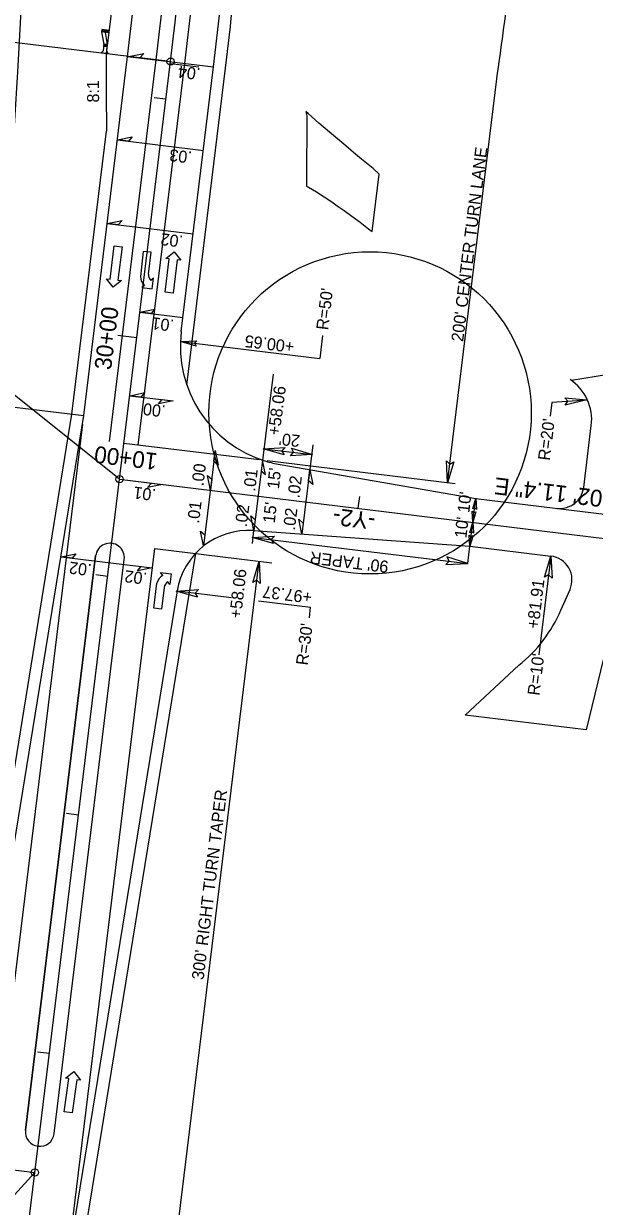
# Model space of a CAD drawing. Extents: x 472216 to 481979, y 489069 to 507339.
# Drawn here: x 481341.2 to 481578.5, y 490719.3 to 491211.4 of the extents above; entities that cross this region are included whole.
import ezdxf

# ---------------------------------------------------------------- set-up
doc = ezdxf.new("R2010")
doc.units = 0
for name, color, linetype in [('Old_Level_12', 7, 'Continuous'), ('Prop Drainage Structure Box Number Symbol CELL', 7, 'Continuous'), ('Prop Drainage Structure Drop Inlet Grate 2 Narrow Slots and Sag Grates 840 24 CELL', 7, 'Continuous'), ('Prop Drainage Structure Drop Inlet Grate 2 Wide Slots and Sag Grates 840 22 Label', 7, 'Continuous'), ('Prop Drainage Structure Outlet Berm Ditch 850 10 CELL', 7, 'Continuous'), ('Prop Drainage Structure Pipe CSP 15in', 7, 'Continuous'), ('Prop Drainage Structure Pipe Plug CELL', 7, 'Continuous'), ('Prop Drainage Structure Pipe RCP 15in Class III Label', 7, 'Continuous'), ('Prop Drainage Structure Pipe RCP 24in Class III Label', 7, 'Continuous'), ('Prop Drainage Structure Pipe Side Drain 15in Label', 7, 'Continuous'), ('Prop Earthen Structure Head Ditch', 7, 'Continuous'), ('Prop Erosion Embankment Toe Protection CELL', 7, 'Continuous'), ('Prop Erosion Embankment Toe Protection Label', 7, 'Continuous'), ('Sheet Block Revision CELL', 7, 'Continuous'), ('Sheet North Arrow Point CELL', 7, 'Continuous'), ('Sheet PE Seal Cell', 7, 'Continuous'), ('Sheet Plan And Profile CELL', 7, 'Continuous'), ('Sheet Plot Border Outside CELL', 7, 'Continuous'), ('Sheet Profile Grid Major CELL', 7, 'Continuous'), ('Sheet Profile Grid Minor CELL', 7, 'Continuous')]:
    doc.layers.add(name, color=color, linetype=linetype)

msp = doc.modelspace()

# ---------------------------------------------------------------- linework, layer by layer
at = {"layer": 'Old_Level_12'}
for p, q in [((481400.78, 491195.76), (481253.89, 491213.7)), ((481381.05, 491021.87), (481307.76, 491080.53)), ((481345.82, 490733.42), (481205.56, 490579.57))]:
    msp.add_line(p, q, dxfattribs=at)
for centre in [(481402.27, 491195.58), (481402.27, 491195.58), (481381.05, 491021.87), (481381.05, 491021.87), (481345.82, 490733.42)]:
    msp.add_circle(centre, 1.5, dxfattribs=at)
at = {"layer": 'Prop Drainage Structure Box Number Symbol CELL'}
msp.add_line((481414.07, 491193.23), (481402.16, 491194.68), dxfattribs=at)
at = {"layer": 'Prop Drainage Structure Drop Inlet Grate 2 Narrow Slots and Sag Grates 840 24 CELL'}
msp.add_line((481440.51, 491029.78), (481440.45, 491029.76), dxfattribs=at)
for points in [[(481384.92, 491197.69), (481391.12, 491198.95), (481389.51, 491197.13)], [(481380.15, 491163.01), (481386.35, 491164.27), (481384.75, 491162.45)], [(481375.91, 491128.27), (481382.11, 491129.53), (481380.5, 491127.71)], [(481389.53, 491091.35), (481395.73, 491092.6), (481394.13, 491090.79)], [(481385.29, 491056.6), (481391.49, 491057.86), (481389.88, 491056.04)], [(481403.39, 491054.39), (481397.19, 491053.14), (481398.8, 491054.95)], [(481420.85, 491033.82), (481422.11, 491027.62), (481420.29, 491029.23)], [(481460.17, 491025.8), (481461.43, 491019.6), (481459.61, 491021.21)], [(481398.92, 491019.68), (481392.72, 491018.42), (481394.32, 491020.24)], [(481418.83, 491017.25), (481417.57, 491023.45), (481419.39, 491021.84)], [(481436.92, 491000.44), (481435.66, 491006.63), (481437.48, 491005.03)], [(481456.9, 490999), (481455.64, 491005.2), (481457.46, 491003.59)], [(481416, 490994.06), (481414.74, 491000.26), (481416.56, 490998.65)], [(481356.72, 490989.57), (481362.92, 490990.83), (481361.31, 490989.01)], [(481394.67, 490984.94), (481388.47, 490983.68), (481390.08, 490985.5)]]:
    msp.add_lwpolyline(points, close=True, dxfattribs=at)
msp.add_lwpolyline([(481440.45, 491029.76), (481439.91, 491025.36), (481441.73, 491023.75), (481440.51, 491029.78)], dxfattribs=at)
at = {"layer": 'Prop Drainage Structure Drop Inlet Grate 2 Wide Slots and Sag Grates 840 22 Label'}
for p, q in [((481384.4, 491197.75), (481420.13, 491193.39)), ((481380.15, 491163.01), (481415.89, 491158.65)), ((481375.91, 491128.27), (481411.65, 491123.91)), ((481389.53, 491091.35), (481407.4, 491089.16)), ((481444.88, 491065.58), (481436.92, 491000.44)), ((481385.29, 491056.6), (481403.16, 491054.42)), ((481441.09, 491034.54), (481460.94, 491032.11)), ((481461.44, 491036.18), (481456.9, 490999)), ((481420.85, 491033.82), (481416, 490994.06)), ((481381.05, 491021.86), (481398.92, 491019.68)), ((481356.72, 490989.57), (481394.67, 490984.94))]:
    msp.add_line(p, q, dxfattribs=at)
at = {"layer": 'Prop Drainage Structure Outlet Berm Ditch 850 10 CELL'}
for points in [[(481412.91, 491077.13), (481406.35, 491079.11), (481413.23, 491079.47), (481412.23, 491078.39)], [(481566.2, 491055.72), (481575.29, 491054.81), (481566.37, 491052.58), (481567.41, 491054.26)], [(481449.51, 491031.96), (481440.74, 491034.52), (481449.91, 491035.08), (481448.59, 491033.62)], [(481452.52, 491034.69), (481461.29, 491032.13), (481452.11, 491031.57), (481453.44, 491033.03)], [(481520.06, 491029.06), (481517.4, 491020.32), (481516.94, 491029.5), (481518.38, 491028.16)], [(481527.9, 491009.5), (481529.17, 491013.89), (481529.46, 491009.3), (481528.73, 491009.96)], [(481529.24, 491008.31), (481527.96, 491003.92), (481527.67, 491008.51), (481528.4, 491007.85)], [(481526.68, 490999.54), (481527.96, 491003.92), (481528.25, 490999.34), (481527.52, 491000)], [(481445, 490995.06), (481436.23, 490997.62), (481445.41, 490998.18), (481444.08, 490996.72)], [(481528.03, 490998.42), (481526.75, 490994.04), (481526.46, 490998.62), (481527.19, 490997.96)], [(481436.43, 490978.94), (481439.09, 490987.68), (481439.55, 490978.5), (481438.11, 490979.84)], [(481516.74, 490986.36), (481525.87, 490986.74), (481517.1, 490989.49), (481518.04, 490987.76)], [(481557.75, 490981.15), (481560.4, 490989.88), (481560.87, 490980.71), (481559.42, 490982.05)], [(481413.41, 490972.77), (481404.64, 490975.33), (481413.81, 490975.89), (481412.49, 490974.43)]]:
    msp.add_lwpolyline(points, close=True, dxfattribs=at)
at = {"layer": 'Prop Drainage Structure Pipe Plug CELL'}
for p, q in [((481381.69, 491248.57), (481375.88, 491202.18)), ((481373.64, 491208.91), (481373.51, 491207.92)), ((481373.51, 491207.92), (481375.16, 491208.72)), ((481376.55, 491207.54), (481373.51, 491207.92)), ((481373.51, 491207.92), (481374.45, 491202.86)), ((481376.68, 491208.53), (481373.64, 491208.91)), ((481375.03, 491207.73), (481373.64, 491208.91)), ((481375.16, 491208.72), (481375.03, 491207.73)), ((481376.68, 491208.53), (481375.03, 491207.73)), ((481375.03, 491207.73), (481375.94, 491202.68)), ((481375.16, 491208.72), (481376.55, 491207.54)), ((481374.45, 491202.86), (481374.33, 491201.87)), ((481374.33, 491201.87), (481375.94, 491202.68)), ((481375.82, 491201.68), (481374.33, 491201.87)), ((481374.37, 491200.25), (481374.59, 491202.29)), ((481374.45, 491202.86), (481374.39, 491202.37)), ((481375.94, 491202.68), (481374.45, 491202.86)), ((481375.82, 491201.68), (481374.45, 491202.86)), ((481374.59, 491202.29), (481375.2, 491202.22)), ((481375.2, 491202.22), (481375.8, 491202.16)), ((481375.8, 491202.16), (481375.58, 491200.12)), ((481373.39, 491199.17), (481374.37, 491200.25)), ((481376.32, 491198.86), (481373.39, 491199.17)), ((481375.58, 491200.12), (481376.32, 491198.86))]:
    msp.add_line(p, q, dxfattribs=at)
at = {"layer": 'Prop Drainage Structure Pipe RCP 15in Class III Label'}
for p, q in [((481376.91, 491037.48), (481396.31, 491196.3)), ((481388.82, 491036.02), (481408.22, 491194.85)), ((481341.92, 490751.02), (481371.1, 490989.94)), ((481371.1, 490989.94), (481341.92, 490751.02)), ((481353.84, 490749.57), (481383.02, 490988.48)), ((481353.84, 490749.57), (481383.02, 490988.48))]:
    msp.add_line(p, q, dxfattribs=at)
for centre, radius, start, end in [((479903.4, 491378.64), 1504, 353.03651, 0.24575), ((479903.4, 491378.64), 1516, 353.03651, 0.24575), ((481377.06, 490989.21), 6, 353.0365, 173.0365), ((481377.06, 490989.21), 6, 353.0365, 173.0365), ((481347.88, 490750.29), 6, 173.0365, 353.0365), ((481347.88, 490750.29), 6, 173.0365, 353.0365)]:
    msp.add_arc(centre, radius, start, end, dxfattribs=at)
at = {"layer": 'Prop Drainage Structure Pipe RCP 24in Class III Label'}
for p, q in [((481366.14, 491048.28), (481384.4, 491197.76)), ((481406.68, 491083.27), (481420.13, 491193.39)), ((481568.91, 491062.98), (481596.21, 491067.55)), ((481322.63, 490780.38), (481366.14, 491048.28)), ((481574.07, 491018.43), (481577.22, 491044.18)), ((481447.78, 491027.94), (481529.17, 491013.85)), ((481529.17, 491013.85), (481693.34, 490993.8)), ((481436.75, 491000.45), (481526.74, 490994)), ((481526.74, 490994), (481560.4, 490989.88)), ((481404.99, 490975.35), (481359.1, 490693.69)), ((481564.58, 490967.3), (481568.36, 490975.96)), ((481589.52, 490977.4), (481575.09, 490917.57)), ((481547.09, 490944.45), (481524.73, 490923.72)), ((481575.09, 490917.57), (481524.73, 490923.72))]:
    msp.add_line(p, q, dxfattribs=at)
for centre, radius, start, end in [((479903.4, 491378.64), 1492, 353.03651, 0.2515), ((479903.4, 491378.64), 1528, 353.03651, 0.25136), ((481456.31, 491077.21), 50, 173.0365, 253.1553), ((481557.37, 491046.61), 20, 353.0092, 56.5397), ((481456.31, 491077.21), 50, 253.1553, 260.1741), ((481564.14, 491019.65), 10, 263.0365, 353.0092), ((481434.6, 490970.53), 30, 85.8989, 170.7459), ((481559.19, 490979.96), 10, 336.4429, 83.0365), ((481509.58, 490991.28), 60, 308.6877, 336.4429)]:
    msp.add_arc(centre, radius, start, end, dxfattribs=at)
at = {"layer": 'Prop Drainage Structure Pipe Side Drain 15in Label'}
for p, q in [((481377.09, 491105.03), (481378.79, 491118.93)), ((481378.79, 491118.93), (481382.06, 491118.53)), ((481382.06, 491118.53), (481380.37, 491104.63)), ((481390.83, 491116.63), (481389.7, 491106.14)), ((481394.12, 491116.28), (481390.83, 491116.63)), ((481393.14, 491107.18), (481394.12, 491116.28)), ((481400.03, 491099.62), (481401.73, 491113.52)), ((481400.24, 491113.7), (481403.7, 491116.45)), ((481401.73, 491113.52), (481400.24, 491113.7)), ((481405, 491113.12), (481403.3, 491099.22)), ((481403.7, 491116.45), (481406.49, 491112.94)), ((481406.49, 491112.94), (481405, 491113.12)), ((481378.4, 491101.7), (481375.6, 491105.21)), ((481375.6, 491105.21), (481377.09, 491105.03)), ((481381.85, 491104.45), (481378.4, 491101.7)), ((481380.37, 491104.63), (481381.85, 491104.45)), ((481395.17, 491105.5), (481394.01, 491104.57)), ((481394.64, 491101.03), (481395.17, 491105.5)), ((481391.42, 491102.48), (481390.27, 491101.55)), ((481390.27, 491101.55), (481394.64, 491101.03)), ((481403.3, 491099.22), (481400.03, 491099.62)), ((481399.03, 490981.8), (481398.12, 490982.97)), ((481398.12, 490982.97), (481402.49, 490982.49)), ((481402.49, 490982.49), (481401.99, 490978.02)), ((481395.25, 490968.16), (481396.53, 490978.63)), ((481399.64, 490976.84), (481398.53, 490967.76)), ((481401.99, 490978.02), (481401.08, 490979.19)), ((481398.53, 490967.76), (481395.25, 490968.16)), ((481358.53, 490772.7), (481362.05, 490775.38)), ((481362.05, 490775.38), (481364.77, 490771.81)), ((481358.04, 490758.63), (481360.02, 490772.49)), ((481360.02, 490772.49), (481358.53, 490772.7)), ((481363.28, 490772.03), (481361.31, 490758.17)), ((481364.77, 490771.81), (481363.28, 490772.03)), ((481361.31, 490758.17), (481358.04, 490758.63))]:
    msp.add_line(p, q, dxfattribs=at)
for centre, radius, start, end in [((481394.94, 491106.37), 5.25, 182.5311, 227.8427), ((481396.37, 491106.82), 3.27, 173.855, 223.5132), ((481401.57, 490977.22), 5.25, 119.0478, 164.3595), ((481402.87, 490976.46), 3.27, 123.3774, 173.0356)]:
    msp.add_arc(centre, radius, start, end, dxfattribs=at)
at = {"layer": 'Prop Earthen Structure Head Ditch'}
for p, q in [((481458.54, 491174.82), (481458.72, 491173.87)), ((481458.72, 491173.87), (481458.93, 491172.77)), ((481486.08, 491124.85), (481489.01, 491148.81))]:
    msp.add_line(p, q, dxfattribs=at)
for points in [[(481489.01, 491148.81), (481486.48, 491151.06), (481484.45, 491152.74), (481481.72, 491155.02), (481478.35, 491157.83), (481475.12, 491160.52), (481470.78, 491164.1), (481468.29, 491166.17), (481463.91, 491170.01), (481459.46, 491173.99), (481458.54, 491174.82)], [(481458.93, 491172.77), (481458.75, 491146.35), (481458.74, 491143.79)], [(481458.74, 491143.79), (481459.58, 491143.34), (481462.97, 491141.34), (481466.11, 491139.36), (481469.28, 491137.23), (481471.56, 491135.64), (481474.49, 491133.57), (481477.68, 491131.25), (481481.05, 491128.72), (481484.56, 491126.03), (481486.08, 491124.85)]]:
    msp.add_lwpolyline(points, dxfattribs=at)
at = {"layer": 'Prop Erosion Embankment Toe Protection CELL'}
for p, q in [((481381.69, 491248.57), (481375.48, 491198.95)), ((481409, 491061.03), (481425.1, 491192.79)), ((481361.18, 491048.88), (481375.57, 491166.71)), ((481315.03, 490764.81), (481361.18, 491048.88)), ((481412.59, 490990.91), (481364.05, 490692.98))]:
    msp.add_line(p, q, dxfattribs=at)
msp.add_arc((479903.4, 491378.64), 1533, 353.03651, 357.21325, dxfattribs=at)
msp.add_spline([(481375.48, 491198.95), (481375.48, 491198.52), (481375.48, 491198.08), (481375.48, 491197.65), (481375.48, 491197.21), (481375.48, 491196.77), (481375.48, 491196.34), (481375.49, 491195.9), (481375.49, 491195.47), (481375.49, 491195.03), (481375.49, 491194.6), (481375.49, 491194.16), (481375.49, 491193.72), (481375.49, 491193.29), (481375.49, 491192.85), (481375.5, 491192.42), (481375.5, 491191.98), (481375.5, 491191.55), (481375.5, 491191.11), (481375.5, 491190.67), (481375.5, 491190.24), (481375.5, 491189.8), (481375.5, 491189.37), (481375.51, 491188.93), (481375.51, 491188.49), (481375.51, 491188.06), (481375.51, 491187.62), (481375.51, 491187.19), (481375.51, 491186.75), (481375.51, 491186.32), (481375.51, 491185.88), (481375.52, 491185.44), (481375.52, 491185.01), (481375.52, 491184.57), (481375.52, 491184.14), (481375.52, 491183.7), (481375.52, 491183.27), (481375.52, 491182.83), (481375.52, 491182.39), (481375.53, 491181.96), (481375.53, 491181.52), (481375.53, 491181.09), (481375.53, 491180.65), (481375.53, 491180.21), (481375.53, 491179.78), (481375.53, 491179.34), (481375.53, 491178.91), (481375.54, 491178.47), (481375.54, 491178.04), (481375.54, 491177.6), (481375.54, 491177.16), (481375.54, 491176.73), (481375.54, 491176.29), (481375.54, 491175.86), (481375.54, 491175.42), (481375.54, 491174.99), (481375.55, 491174.55), (481375.55, 491174.11), (481375.55, 491173.68), (481375.55, 491173.24), (481375.55, 491172.81), (481375.55, 491172.37), (481375.55, 491171.93), (481375.55, 491171.5), (481375.56, 491171.06), (481375.56, 491170.63), (481375.56, 491170.19), (481375.56, 491169.76), (481375.56, 491169.32), (481375.56, 491168.88), (481375.56, 491168.45), (481375.56, 491168.01), (481375.57, 491167.58), (481375.57, 491166.71)], degree=3, dxfattribs=at)
at = {"layer": 'Prop Erosion Embankment Toe Protection Label'}
for p, q in [((481329.34, 490746.99), (481365.71, 491044.78)), ((481359.1, 490693.69), (481395.65, 490992.98))]:
    msp.add_line(p, q, dxfattribs=at)
at = {"layer": 'Sheet Block Revision CELL'}
for p, q in [((481517.4, 491020.32), (481537.92, 491188.37)), ((481406.35, 491079.11), (481464.26, 491072.03)), ((481465.44, 491081.68), (481464.26, 491072.03)), ((481291.41, 491057.4), (481366.14, 491048.28)), ((481575.63, 491054.77), (481560.85, 491053.69)), ((481560.85, 491053.69), (481560.16, 491048.1)), ((481439.2, 491029.87), (481382.87, 491036.75)), ((481520.67, 491019.92), (481442.38, 491029.48)), ((481526.74, 490994), (481529.18, 491013.85)), ((481436.27, 490995.11), (481436.92, 491000.44)), ((481436.59, 490997.64), (481525.87, 490986.74)), ((481395.65, 490992.98), (481444.39, 490987.03)), ((481525.87, 490986.74), (481526.76, 490993.99)), ((481402.53, 490688.38), (481439.09, 490987.68)), ((481560.4, 490989.88), (481555.39, 490948.81)), ((481404.99, 490975.35), (481427.53, 490972.6)), ((481438.82, 490971.22), (481460.49, 490968.57)), ((481459.96, 490964.23), (481460.49, 490968.57))]:
    msp.add_line(p, q, dxfattribs=at)
msp.add_arc((478970.41, 491554.36), 2593.46, 351.88804, 352.74017, dxfattribs=at)
at = {"layer": 'Sheet North Arrow Point CELL'}
for p, q in [((481200.24, 489541.46), (481402.27, 491195.58)), ((481381.05, 491021.87), (481684.64, 490984.78)), ((481273.15, 490742.29), (481345.82, 490733.42))]:
    msp.add_line(p, q, dxfattribs=at)
for centre, radius, end in [((478448.7, 491360.28), 2895, 18.70399), ((479903.4, 491378.64), 1510, 12.98112)]:
    msp.add_arc(centre, radius, 353.03651, end, dxfattribs=at)
at = {"layer": 'Sheet PE Seal Cell'}
for p, q in [((481400.35, 491179.93), (481395.39, 491180.53)), ((481480.31, 491009.74), (481480.92, 491014.7)), ((481376.11, 490981.4), (481371.14, 490982.01)), ((481363.98, 490882.14), (481359.02, 490882.75)), ((481351.86, 490782.88), (481346.9, 490783.48))]:
    msp.add_line(p, q, dxfattribs=at)
at = {"layer": 'Sheet Plot Border Outside CELL'}
msp.add_circle((481485.2, 491049.44), 67.03, dxfattribs=at)
at = {"layer": 'Sheet Profile Grid Minor CELL'}
for p, q in [((481388.23, 491080.67), (481380.29, 491081.64)), ((481381.05, 491021.87), (481382.02, 491029.81)), ((481381.05, 491021.87), (481382.02, 491029.81)), ((481345.82, 490733.42), (481346.79, 490741.36))]:
    msp.add_line(p, q, dxfattribs=at)

# ---------------------------------------------------------------- texts
at = {"layer": 'Prop Drainage Structure Drop Inlet Grate 2 Narrow Slots and Sag Grates 840 24 CELL'}
for s, rotation, p in [('.04', 173.0359, (481414.89, 491192.81)), ('.03', 173.0359, (481411.36, 491158.09)), ('.02', 173.0359, (481407.69, 491123.12)), ('.01', 173.0359, (481403.94, 491088.16)), ('.00', 173.0359, (481400.37, 491052.46)), ('.00', 83.0368, (481415.9, 491018.81)), ('.01', 83.0368, (481437.42, 491016.58)), ('.02', 83.0368, (481455.79, 491013.76)), ('.01', 173.0359, (481396.42, 491017.68)), ('.01', 83.0368, (481414.07, 491003.26)), ('.02', 83.0368, (481433.94, 491001.81)), ('.02', 83.0368, (481453.92, 491000.38)), ('.02', 173.0359, (481369.64, 490986.44)), ('.02', 173.0359, (481392.71, 490982.87))]:
    msp.add_text(s, height=5, rotation=rotation, dxfattribs=at).set_placement(p)
at = {"layer": 'Prop Drainage Structure Drop Inlet Grate 2 Wide Slots and Sag Grates 840 22 Label'}
for s, rotation, p in [('+58.06', 82.3928, (481447.54, 491039.84)), ("20'", 173.7495, (481456.29, 491040.14)), ('+58.06', 83.6803, (481431.58, 490963.74))]:
    msp.add_text(s, height=5, rotation=rotation, dxfattribs=at).set_placement(p)
at = {"layer": 'Prop Drainage Structure Pipe CSP 15in'}
for s, rotation, p in [('8:1', 90.5984, (481372.56, 491178.58)), ("200' CENTER TURN LANE ", 82.8641, (481523.89, 491078.82)), ("R=50'", 83.0365, (481467.75, 491083.69)), ('+00.65', 173.0365, (481453.92, 491079.32)), ("R=20'", 83.0365, (481559.96, 491029.41)), ("15'", 83.5432, (481447.3, 491017.58)), ("10'", 83.5432, (481526.46, 491007.66)), ("15'", 83.5432, (481445.56, 491003.34)), ("10'", 83.5432, (481525.27, 490997.14)), ("90' TAPER ", 173.0365, (481493.12, 490987.77)), ('+97.37', 173.0365, (481461.32, 490975.04)), ('+81.91', 83.0365, (481555.27, 490959.46)), ("R=30'", 83.0365, (481459.32, 490944.22)), ("R=10'", 83.0365, (481555.6, 490931.66)), ("300' RIGHT TURN TAPER ", 82.8641, (481415.95, 490813.33))]:
    msp.add_text(s, height=5, rotation=rotation, dxfattribs=at).set_placement(p)
at = {"layer": 'Sheet Plan And Profile CELL'}
for s, p in [('S 83%%d 02\' 11.4" E', (481607.64, 491014.04)), ('-Y2-', (481487.74, 491007.74))]:
    msp.add_text(s, height=7, rotation=173.0365, dxfattribs=at).set_placement(p)
at = {"layer": 'Sheet Profile Grid Major CELL'}
for s, rotation, p in [('30+00', 83.0365, (481377.5, 491067.04)), ('10+00', 173.0365, (481397.12, 491032.55))]:
    msp.add_text(s, height=7, rotation=rotation, dxfattribs=at).set_placement(p)

doc.saveas('drawing.dxf')
